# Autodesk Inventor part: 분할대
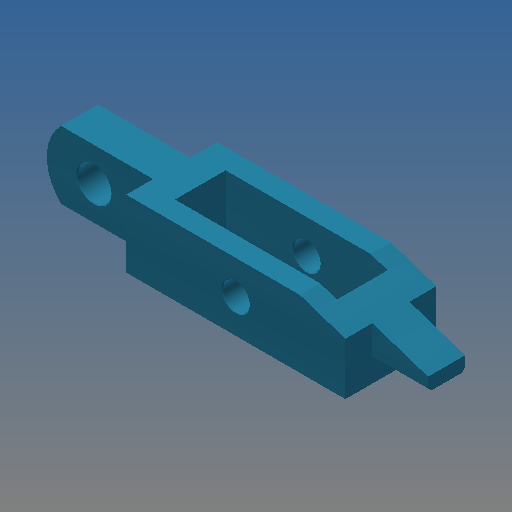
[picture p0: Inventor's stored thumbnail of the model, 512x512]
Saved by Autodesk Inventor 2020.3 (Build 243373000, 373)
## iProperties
Created: 2016-11
Part Number: 분할대
Material: 강철, 연강
Document SubType Name: Modeling
Designer: mduedu
Density: 1 g/cm^3
Appearance: 터키옥색
Author: mduedu
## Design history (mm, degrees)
sketch "스케치1"
  geometry: L1 (32.5, 13.5)-(-32.5, 13.5); L2 (-32.5, 13.5)-(-32.5, -13.5); L3 (-32.5, -13.5)-(32.5, -13.5); L4 (32.5, -13.5)-(32.5, 13.5); L5 (24, 7.5)-(-24, 7.5); L6 (-24, 7.5)-(-24, -7.5); L7 (-24, -7.5)-(24, -7.5); L8 (24, -7.5)-(24, 7.5); L9 (24, 0)-(-24, 0); L10 (0, -13.5)-(0, 13.5); 4 further points
  constraints: 20 end point, 7 midpoint, 4 parallel, 2 coincident, 2 horizontal, 2 perpendicular, 1 horizontal alignment
  dimensions: "d0" = 15 distance of L5.end L6.end; "d2" = 27 distance between parallel lines of L1 L3; "d3" = 48 distance of L5.start L5.end; "d4" = 65 distance of L1.start L1.end
extrude "돌출1" new body sketch "스케치1" distance "d5" = 20; taper "d6" = 0 deg
sketch "스케치2"
  geometry: L1 (0, 0)-(65, 0) reference; L2 (65, 0)-(65, 20) reference; L3 (0, 20)-(65, 20) reference; L4 (0, 0)-(0, 20) reference; L5 (32.5, 0)-(32.5, 20); C1 r 4 at (32.5, 10)
  constraints: 2 end point, 2 midpoint, 1 centre point
  dimensions: "d7" = 8 diameter of C1
extrude "돌출2" cut sketch "스케치2" extent not by distance; stored distance "d8" = 20; taper "d9" = 0 deg
chamfer "모따기1" distance "d10" = 0.2; stored, may be unused: second distance "d11" = 2, angle "d12" = 45 deg
sketch "스케치3"
  geometry: L1 (-32.5, 0)-(-32.5, 20) reference; L2 (-32.5, 20)-(-59.798, 20); L3 (-64, 20)-(-64, 0); L4 (-64, 0)-(-59.798, 0); L5 (-32.5, 0)-(-32.5, 20); L6 (-59.798, 20)-(-64, 20); L7 (-59.798, 0)-(-32.5, 0); C1 r 4.2 at (0, 10) reference; C2 r 5 at (-50, 10); A1 r 14 centre (-50, 10) between (-59.798, 20) and (-59.798, 0); 1 further point
  constraints: 12 end point, 5 parallel, 2 centre point, 2 horizontal, 2 perpendicular, 2 point on circle, 1 coincident, 1 horizontal alignment, 1 tangent
  dimensions: "d13" = 64 distance from line of L3 C1.centre; "d14" = 14 radius of A1; "d15" = 10 diameter of C2
extrude "돌출3" join sketch "스케치3" stored distance "d16" = 11; taper "d17" = 0 deg
sketch "스케치4"
  geometry: L1 (32.5, 0)-(32.5, 20) reference; L2 (32.5, 20)-(49, 20); L3 (49, 20)-(49, 6); L4 (49, 6)-(32.5, 6); L5 (32.5, 6)-(32.5, 20); L6 (32.5, 0)-(-32.5, 0) reference; 1 further point
  constraints: 8 end point, 2 parallel, 1 horizontal, 1 perpendicular
  dimensions: "d18" = 16.5 distance of L1.end L2.end; "d19" = 6 distance between parallel lines of L4 L6
extrude "돌출4" join sketch "스케치4" stored distance "d20" = 11; taper "d21" = 0 deg
chamfer "모따기2" distance "d22" = 30; stored, may be unused: second distance "d23" = 10, angle "d24" = 45 deg
chamfer "모따기3" distance "d25" = 1; stored, may be unused: second distance "d26" = 10, angle "d27" = 45 deg
chamfer "모따기4" distance "d28" = 0.2; stored, may be unused: second distance "d29" = 10, angle "d30" = 45 deg
node "솔리드1"
node "투영된 루프1"
